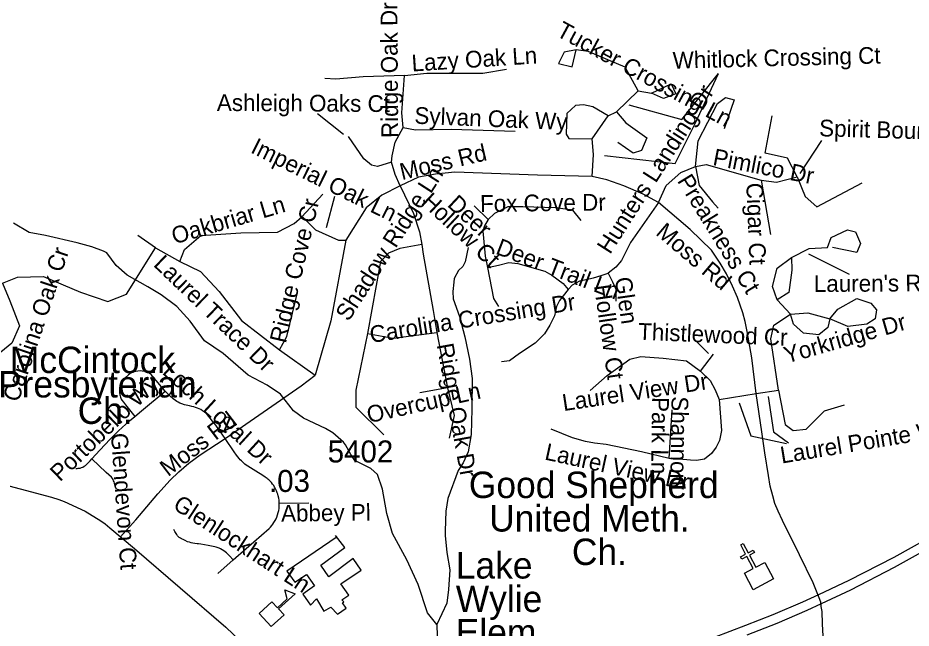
# Model space of a CAD drawing. Extents: x 1383679 to 1536984, y 460658 to 651027.
# Drawn here: x 1408689 to 1413754, y 502468 to 505931 of the extents above; entities that cross this region are included whole.
import ezdxf

# ---------------------------------------------------------------- set-up
doc = ezdxf.new("R2010")
doc.units = 0
for name, color, linetype in [('Exist Cultural Church CELL', 7, 'Continuous'), ('Exist Cultural Church Label', 7, 'Continuous'), ('Exist Cultural Church with Cemetery Label', 7, 'Continuous'), ('Exist Cultural Educational Facility Elementary CELL', 7, 'Continuous'), ('Exist Cultural Educational Facility Elementary Footprint', 7, 'Continuous'), ('Exist Hydrographic Creek Single Shore', 7, 'Continuous'), ('Exist Road Non-System Type 51', 7, 'Continuous'), ('Exist Road Non-System Type 51 Label', 7, 'Continuous'), ('Exist Road Primary NC UnDivided 4 Lane Attributed', 7, 'Continuous'), ('Exist Road Secondary Mileage Hundredths English Label', 7, 'Continuous'), ('Exist Road Secondary Type 51 Attributed', 7, 'Continuous'), ('Exist Road Secondary Type 51 Label', 7, 'Continuous'), ('Exist Road Secondary Type 51 Number Label', 7, 'Continuous')]:
    doc.layers.add(name, color=color, linetype=linetype)

msp = doc.modelspace()

# ---------------------------------------------------------------- linework, layer by layer
at = {"layer": 'Exist Cultural Church CELL'}
msp.add_lwpolyline([(1412808.6, 502780.3), (1412858.9, 502806.9), (1412823.4, 502874.3), (1412795.1, 502859.3), (1412787.6, 502873.5), (1412815.9, 502888.4), (1412787.9, 502941.6), (1412802, 502949.1), (1412830.1, 502895.9), (1412858.4, 502910.8), (1412865.9, 502896.7), (1412837.6, 502881.8), (1412873.1, 502814.4), (1412924.1, 502841.2), (1412973.8, 502747.1), (1412858.3, 502686.1)], close=True, dxfattribs=at)
at = {"layer": 'Exist Cultural Educational Facility Elementary CELL'}
msp.add_lwpolyline([(1410057, 502551.6), (1410129.3, 502617.7), (1410160.3, 502583.7), (1410215.7, 502634.4), (1410201.9, 502685.5), (1410261.6, 502663.4), (1410166.8, 502576.6), (1410197.9, 502542.7), (1410125.6, 502476.6)], close=True, dxfattribs=at)
at = {"layer": 'Exist Cultural Educational Facility Elementary Footprint'}
msp.add_lwpolyline([(1410500, 502985.4), (1410214.1, 502790.9), (1410258.9, 502728), (1410324.6, 502772.8), (1410371.3, 502708), (1410303.7, 502660.3), (1410347.5, 502597.4), (1410381.3, 502633.5), (1410424.5, 502563.7), (1410463.8, 502587.9), (1410501.9, 502547.8), (1410549.6, 502582.1), (1410529.6, 502610.7), (1410537.2, 502616.5), (1410525.8, 502628.8), (1410564.8, 502655.5), (1410519.5, 502720.1), (1410636.3, 502797.6), (1410589.6, 502862.4), (1410452.4, 502759.4), (1410407.6, 502826.2), (1410542, 502925.3), (1410490.7, 502993.8)], dxfattribs=at)
at = {"layer": 'Exist Hydrographic Creek Single Shore'}
for points in [[(1411063.7, 502487.9), (1411011, 502555.4), (1410958.1, 502716.5), (1410894.9, 502855.6), (1410813.6, 503005), (1410781.9, 503118), (1410756.6, 503256.4), (1410728.2, 503340.7), (1410690.8, 503373.4), (1410599.6, 503419.6), (1410576.3, 503453.7), (1410547.3, 503508.5), (1410535.6, 503522.7), (1410474.6, 503576.4), (1410433.1, 503601), (1410308.2, 503659.3), (1410251, 503700.7), (1410178.9, 503795.7), (1410101.9, 503847.3), (1409994.8, 503903.7), (1409853.2, 504026.3), (1409746.5, 504098.2), (1409666.6, 504209.7), (1409590.3, 504293.4), (1409501.5, 504359.1), (1409426.3, 504405), (1409307.6, 504471.4), (1409246.6, 504526.8), (1409194, 504597.5), (1409174.2, 504607.8), (1409108.6, 504631.3), (1409025, 504655.1), (1408845.8, 504696.5), (1408752, 504712.3), (1408663, 504765.8)], [(1411241.5, 504627.7), (1411226.1, 504547.6), (1411211.4, 504520), (1411187, 504498.4), (1411162.2, 504452.9), (1411161.7, 504430.7), (1411154.6, 504379.2), (1411157.9, 504337.3), (1411193.9, 504236.5), (1411223.7, 504121.8), (1411249.2, 503994.9), (1411265, 503884.6), (1411263.6, 503710.7), (1411258.9, 503567.2), (1411243, 503469), (1411213.7, 503405.6), (1411184.8, 503361.9), (1411127.7, 503203), (1411116.3, 503131), (1411112.2, 503019.5), (1411111.6, 502993.3), (1411121.8, 502897.1), (1411137.9, 502799.1), (1411131.5, 502686.8), (1411122.1, 502610.6), (1411063.7, 502487.9)], [(1411063.7, 502487.9), (1411069.9, 502294.1), (1411080, 502088), (1411089.7, 501971.2), (1411101.1, 501843), (1411167, 501529.8), (1411204.6, 501405.1), (1411274.6, 501193.7), (1411312.1, 501066.6), (1411376.4, 500877.3), (1411399.3, 500822.7)]]:
    msp.add_lwpolyline(points, dxfattribs=at)
at = {"layer": 'Exist Road Non-System Type 51'}
for p, q in [((1411356.4, 504787.1), (1411277.1, 504864.1)), ((1412560.6, 503926.4), (1412634.3, 504023.3)), ((1412665.2, 503765), (1412875.9, 503799.1)), ((1412382.4, 503430.6), (1412399, 503707.3)), ((1409822.7, 502778.9), (1409909.5, 502855.6))]:
    msp.add_line(p, q, dxfattribs=at)
for points in [[(1412205.5, 505517), (1412132.2, 505651), (1411922.4, 505739.6), (1411854.1, 505749.7), (1411785.9, 505737), (1411755.5, 505671.3), (1411831.4, 505653.5), (1411854.1, 505749.7)], [(1410880.6, 505603.3), (1411008.2, 505616.7), (1411180.6, 505616.7), (1411325.4, 505616.7), (1411459.8, 505640.1)], [(1410880.6, 505603.3), (1410646.2, 505596.7), (1410491.1, 505583.3), (1410429, 505586.6)], [(1410873.8, 505309), (1410866.9, 505392.6), (1410880.6, 505603.3)], [(1412014.7, 505150.5), (1412416.3, 505104), (1412530.5, 505332.5), (1412661.5, 505616)], [(1412154.2, 505438.2), (1412454.4, 505353.6), (1412661.5, 505616)], [(1412084.2, 505398.1), (1412205.5, 505517), (1412281.4, 505504.3), (1412392.6, 505557.4), (1412420.4, 505499.2), (1412349.6, 505473.9), (1412281.4, 505504.3)], [(1412531.7, 505086.9), (1412546.8, 505233.6), (1412655.5, 505446.1), (1412701, 505479), (1412751.6, 505466.4), (1412693.5, 505301.9)], [(1411945.1, 505243.8), (1412036.2, 505375.3), (1411950.2, 505425.9), (1411897.1, 505438.5), (1411851.6, 505433.5), (1411801, 505387.9), (1411798.5, 505271.6), (1411813.7, 505246.3), (1411945.1, 505243.8)], [(1410535.9, 505268.5), (1410387.9, 505387)], [(1412036.2, 505375.3), (1412084.2, 505398.1), (1412137.3, 505334.8), (1412256.1, 505251.3), (1412225.8, 505178), (1412177.7, 505162.8), (1412091.8, 505223.5)], [(1413108.1, 505028.7), (1413052.4, 505135), (1412926, 505162.8), (1412966.5, 505375.3)], [(1410808.3, 505111.6), (1410811.7, 505148.4), (1410828.9, 505225.3), (1410873.8, 505309)], [(1410873.8, 505309), (1410942.7, 505295.6), (1411146.1, 505298.9), (1411508.1, 505288.9)], [(1410808.3, 505111.6), (1410729, 505088.2), (1410694.5, 505094.9), (1410649.7, 505131.7), (1410563.5, 505258.8)], [(1411945.9, 505031.3), (1411952.8, 505155.1), (1411945.1, 505243.8)], [(1413125.1, 505048.8), (1413247.8, 505234.9)], [(1410856.5, 504977.8), (1410828.9, 505041.4), (1410808.3, 505111.6)], [(1412321.6, 504884.1), (1412364.8, 504980.7), (1412448.2, 505054), (1412531.7, 505086.9), (1412551.9, 504980.7), (1412627.7, 504887.1), (1412660.6, 504851.7)], [(1412531.7, 505086.9), (1412592.3, 505099.6), (1412903.3, 505011), (1412991.8, 504998.4), (1413108.1, 505028.7)], [(1411945.9, 505031.3), (1411635.6, 505038), (1411166.8, 505054.7), (1411056.5, 505044.7), (1410959.9, 505028), (1410856.5, 504977.8)], [(1412321.6, 504884.1), (1412235.4, 504931), (1412125.1, 504977.8), (1412028.6, 505011.3), (1411945.9, 505031.3)], [(1413108.1, 505028.7), (1413153.6, 504917.4), (1413219.3, 504859.3), (1413477.2, 504995.9)], [(1410856.5, 504977.8), (1410753.1, 504924.3), (1410663.5, 504854), (1410548.3, 504670.5)], [(1410856.5, 504977.8), (1410932.4, 504820.6), (1410966.8, 504716.9), (1410979.9, 504645.3), (1410987.5, 504589.8), (1411044.4, 504270), (1411064.7, 504145.6), (1411124.4, 503831.3), (1411162.1, 503674.1), (1411133.8, 503545.2)], [(1412903.3, 505011), (1412956.4, 504702.4)], [(1409607.8, 504547.9), (1409632.9, 504617.1), (1409727.1, 504695.6), (1409953.3, 504711.3), (1410160.6, 504714.5), (1410254.9, 504764.8), (1410298.9, 504802.5), (1410418.2, 504931.4)], [(1410439.5, 504740.8), (1410486, 504918.5)], [(1412321.6, 504884.1), (1412163.1, 504656.7), (1412111.5, 504553.7), (1412080.6, 504516.8), (1412035.4, 504482.2)], [(1412875.9, 503799.1), (1412850.5, 504001.9), (1412824.9, 504152.1), (1412812.9, 504207.8), (1412800.1, 504256.7), (1412770.1, 504344.7), (1412741.9, 504409.5), (1412706.8, 504479.2), (1412670.9, 504539.8), (1412645.2, 504578.8), (1412622.1, 504612.9), (1412500.9, 504730.3), (1412321.6, 504884.1)], [(1411883.8, 504780.4), (1411835.6, 504840.2), (1411738.2, 504852.8), (1411552.9, 504859.1), (1411468.1, 504859.1), (1411390.9, 504820.6), (1411356.4, 504787.1)], [(1410304.2, 504800), (1410376.1, 504728.1), (1410507.1, 504668.8), (1410548.3, 504670.5)], [(1411356.4, 504787.1), (1411335.7, 504750.3), (1411325.4, 504720.2), (1411328.8, 504680.1), (1411339.1, 504579.7), (1411351, 504514.5)], [(1413075.2, 504571.9), (1413176.3, 504622.5), (1413280, 504627.5), (1413300.2, 504685.7), (1413393.7, 504728.7), (1413439.2, 504716.1), (1413467.1, 504650.3), (1413446.8, 504599.7), (1413307.8, 504627.5)], [(1409468.3, 504626.5), (1409369, 504695.6)], [(1410548.3, 504670.5), (1410463.5, 504211.6), (1410374.3, 503903.5)], [(1408601.3, 504425.3), (1408686.1, 504459.9), (1408833.7, 504463), (1409044.2, 504375), (1409198.1, 504321.6), (1409304.9, 504362.5), (1409468.3, 504626.5)], [(1409468.3, 504626.5), (1409607.8, 504547.9), (1409724, 504491.3), (1409830.8, 504378.2), (1409956.5, 504214.7), (1410173.2, 504048.1), (1410374.3, 503903.5)], [(1410979.9, 504645.3), (1410854.2, 504623.3), (1410791.4, 504595.1), (1410744.3, 504547.9), (1410672, 504139.3), (1410606.1, 503818.7), (1410606.1, 503721.2), (1410763.1, 503564.1)], [(1413001.9, 503818.1), (1412958.9, 504109), (1412976.6, 504187.4), (1413070.1, 504250.6), (1413168.7, 504258.2), (1413292.6, 504222.8), (1413338.1, 504278.5), (1413446.8, 504339.2), (1413525.2, 504311.3), (1413558.1, 504273.4), (1413550.5, 504222.8), (1413502.5, 504192.5), (1413396.3, 504179.8), (1413292.6, 504222.8), (1413282.5, 504174.7), (1413231.9, 504131.7), (1413143.5, 504141.9), (1413087.8, 504192.5), (1413070.1, 504250.6), (1412994.3, 504331.6), (1412969, 504407.5), (1412994.3, 504511.2), (1413075.2, 504571.9), (1413077.7, 504498.5), (1413060, 504372.1), (1412994.3, 504331.6)], [(1413172.7, 504591.2), (1413402.8, 504476.1)], [(1411351, 504514.5), (1411415.2, 504528.3), (1411472.2, 504542.2), (1411524.5, 504537.5), (1411676.6, 504493.7), (1411717, 504470.7), (1411781.1, 504424.5), (1411809.7, 504390)], [(1411351, 504514.5), (1411386.6, 504339.2), (1411415.2, 504293.1)], [(1411809.7, 504390), (1411833.4, 504415.3), (1411876.2, 504438.4), (1411952.2, 504456.8), (1411997.4, 504468.4), (1412035.4, 504482.2)], [(1412035.4, 504482.2), (1412061.6, 504433.8), (1412080.6, 504392.3), (1412080.6, 504323.1)], [(1408601.3, 504425.3), (1408642.1, 504324.7), (1408698.7, 504183.3), (1408654.7, 504085.9), (1408538.5, 503991.6), (1408387.7, 503834.4), (1408334.3, 503667.8)], [(1410173.2, 504048.1), (1410214, 504123.6), (1410273.7, 504371.9)], [(1411809.7, 504390), (1411759.8, 504327.7), (1411743.1, 504293.1), (1411731.2, 504240.1), (1411706.3, 504188.2), (1411675.4, 504137.5), (1411622, 504085.9), (1411534, 504026.1), (1411477.5, 503985.3), (1411430.4, 503979)], [(1406959.6, 504223.3), (1407037.3, 504172.6), (1408317.7, 503410), (1408372.3, 503379.1), (1408441.3, 503342.5), (1408522.5, 503306.6), (1408879.4, 503210.4), (1408921.1, 503197.4), (1408951.9, 503186.9), (1409070.9, 503132.4), (1409159.8, 503076.8), (1409182.8, 503060), (1409210.2, 503037.9), (1409349.6, 502919.9), (1409868.6, 502473.9), (1409990.9, 502356.1), (1410024.8, 502313.2), (1410047, 502279.4), (1410104.6, 502177.8), (1410133.3, 502110.2), (1410384.7, 501515.1)], [(1410672, 504139.3), (1410816.6, 504114.1), (1411064.7, 504145.6)], [(1412605.1, 504025.9), (1412533.2, 504097.9)], [(1411934.4, 503817.4), (1412031.1, 503901.6), (1412159.2, 503994.4), (1412220.7, 504010.3), (1412348.7, 503999.3), (1412480.1, 503984.2), (1412560.6, 503926.4)], [(1409524.8, 503812.5), (1409452.8, 503897), (1409443.8, 503906.4), (1409438.5, 503910.8), (1409429.4, 503916.7), (1409419.7, 503921.3), (1409412.8, 503923.7), (1409407, 503925.2), (1409393.1, 503926.9), (1409381.2, 503927.4), (1409368.3, 503926.7), (1409357.6, 503924.7), (1409350.2, 503923), (1409342.9, 503920.7), (1409331.7, 503916.1), (1409324.4, 503911.3), (1409316.6, 503905.7), (1409299.8, 503890.8), (1409288.3, 503879.4), (1409281.3, 503871.4), (1409275.4, 503863.6), (1409272.2, 503858.2), (1409269.1, 503851.1), (1409267.4, 503845.5), (1409266.6, 503841.3), (1409265.6, 503832.8), (1409265.2, 503822.8), (1409265.2, 503814.8), (1409265.4, 503805.1), (1409266.6, 503792.6), (1409268.1, 503785.6), (1409270, 503778.7), (1409272.5, 503772.2), (1409275.2, 503767.3), (1409278.8, 503761.7), (1409286.8, 503750.5), (1409299.6, 503734.4), (1409351.3, 503668.9)], [(1412560.6, 503926.4), (1412615.3, 503873.4), (1412643.8, 503820.3), (1412665.2, 503765)], [(1409863.5, 503544.8), (1410295.7, 503843.8), (1410374.3, 503903.5)], [(1409351.3, 503668.9), (1409390.3, 503701), (1409524.8, 503812.5)], [(1409863.5, 503544.8), (1409838, 503582.2), (1409805.6, 503627.2), (1409793.1, 503643.1), (1409779.7, 503659.9), (1409772, 503668.8), (1409762.1, 503679.5), (1409754.1, 503688), (1409746.4, 503694.4), (1409736.4, 503701.7), (1409725.9, 503707.9), (1409717, 503712.6), (1409706.8, 503716.3), (1409701.6, 503718.4), (1409695.3, 503720.5), (1409686.1, 503723.1), (1409674.8, 503726), (1409661.3, 503729.3), (1409632.8, 503735.9), (1409618.3, 503740.5), (1409607.6, 503744.7), (1409597.9, 503749.4), (1409590.9, 503753.6), (1409582, 503759.6), (1409569.6, 503769), (1409562.9, 503774.5), (1409555.8, 503780.9), (1409538.9, 503797.2), (1409524.8, 503812.5)], [(1411124.4, 503831.3), (1410967.3, 503803)], [(1412875.9, 503799.1), (1413001.9, 503818.1)], [(1413001.9, 503818.1), (1413039.8, 503623.3), (1413085.3, 503590.4), (1413158.6, 503598), (1413262.3, 503701.7), (1413376, 503734.6)], [(1412665.2, 503765), (1412679.4, 503589.7), (1412668.2, 503533.2), (1412648.3, 503495.5), (1412622.2, 503458.6), (1412582.2, 503427), (1412536.7, 503419.4), (1412503.9, 503421.9), (1412438.1, 503427), (1412382.4, 503430.6)], [(1413233.8, 502640.5), (1413197.9, 502724.3), (1413121.8, 502883.7), (1413025.1, 503078.8), (1413000.3, 503132.7), (1412982.3, 503175.9), (1412969.5, 503218.2), (1412955.8, 503273.9), (1412945.5, 503334.5), (1412925, 503463.1), (1412907.9, 503582.7), (1412875.9, 503799.1)], [(1412944, 503782), (1412974.1, 503581.9), (1413059, 503518.8)], [(1412779.6, 503746.4), (1412845.3, 503559.9), (1413048.1, 503516)], [(1409108.3, 503427.9), (1409153.1, 503478.3), (1409211.6, 503540.2), (1409259.6, 503587.2), (1409321.1, 503644.1), (1409351.3, 503668.9)], [(1412382.4, 503430.6), (1412226.2, 503468.6), (1412024.1, 503510.6), (1411958.1, 503516.9), (1411907.8, 503526.4), (1411834.8, 503548.1), (1411713.6, 503596.5)], [(1409269.5, 502984.7), (1409357, 503082.7), (1409483.1, 503230.3), (1409551.8, 503307.1), (1409600.8, 503355.6), (1409658.1, 503405.1), (1409721.6, 503451.6), (1409863.5, 503544.8)], [(1410171, 503177.8), (1410170.9, 503181.6), (1410169.7, 503194), (1410167.9, 503205.6), (1410165.1, 503218.2), (1410162.4, 503227.7), (1410159.8, 503235.1), (1410155.2, 503246.6), (1410149.5, 503258.4), (1410143.8, 503268.6), (1410139.6, 503276.9), (1410133.2, 503285.8), (1410126.3, 503294.2), (1410119.5, 503301.6), (1410111.6, 503308.9), (1410105.6, 503313.9), (1410101.9, 503317), (1410091.4, 503324.7), (1410078, 503333.5), (1410038.1, 503359.1), (1410007.4, 503377.7), (1409992.5, 503387.2), (1409983.9, 503392.9), (1409975.4, 503399.3), (1409967.3, 503406.3), (1409956, 503417.1), (1409950, 503423.4), (1409943.7, 503430.5), (1409928.8, 503448.7), (1409915.2, 503467.6), (1409863.5, 503544.8)], [(1409016.5, 503373.5), (1409024.6, 503374.2), (1409029.9, 503374.9), (1409041.2, 503376.7), (1409048.6, 503378.7), (1409056.4, 503382), (1409064.5, 503386.6), (1409071.3, 503391.2), (1409079.2, 503398.3), (1409098.6, 503417), (1409108.3, 503427.9)], [(1409241.5, 503266.7), (1409238.8, 503281), (1409236.8, 503290.3), (1409234.4, 503297.8), (1409231.3, 503304.8), (1409228.2, 503310.6), (1409224.7, 503316.5), (1409219.2, 503323.8), (1409189.9, 503351.8), (1409108.3, 503427.9)], [(1409909.5, 502855.6), (1409982.8, 502920.4), (1410113, 503034.2), (1410120.4, 503041.7), (1410128.2, 503050.7), (1410134.5, 503058.7), (1410140.8, 503067.9), (1410147.2, 503078.4), (1410152.7, 503088.6), (1410156.9, 503098.4), (1410161.7, 503111.4), (1410165.2, 503123.3), (1410168, 503135.7), (1410169.8, 503147.3), (1410171, 503161), (1410171.2, 503172.1), (1410171, 503177.8)], [(1409909.5, 502855.6), (1409889.6, 502877.7), (1409883.4, 502883.7), (1409876.6, 502890.5), (1409871.4, 502895.1), (1409864.1, 502901.3), (1409857.1, 502906.4), (1409847.2, 502912.9), (1409837.7, 502918.2), (1409830.9, 502921.7), (1409825.4, 502924.1), (1409818.6, 502926.4), (1409812.3, 502928.3), (1409805, 502930.2), (1409786.3, 502934), (1409767.8, 502937.3), (1409746.7, 502940.6), (1409726.7, 502944.1), (1409713.8, 502945.8), (1409705.2, 502946.8), (1409691.6, 502948.5), (1409680.2, 502950.2), (1409670.7, 502952.2), (1409661.6, 502955), (1409650.7, 502958.5), (1409637.7, 502964.4), (1409625.5, 502970.5), (1409616.8, 502975.4), (1409610.8, 502978.7), (1409603.9, 502983.1), (1409597.8, 502987.5), (1409593.9, 502992.5), (1409590.3, 502998.7), (1409585.9, 503004.9), (1409579.6, 503015.8), (1409572.9, 503027.6)], [(1413255.6, 502422.7), (1413252.1, 502492.9), (1413249.2, 502561.6), (1413245, 502591.5), (1413242.4, 502614.7), (1413233.8, 502640.5)]]:
    msp.add_lwpolyline(points, dxfattribs=at)
at = {"layer": 'Exist Road Primary NC UnDivided 4 Lane Attributed'}
for points in [[(1412640.1, 502416.6), (1412816.7, 502485.5), (1412971.9, 502545.9), (1413140.7, 502618), (1413230.5, 502659.8), (1413403.2, 502739.6), (1413658, 502871.3), (1413935.6, 503026.3), (1414353.7, 503262.6), (1414637.9, 503426)], [(1412824.4, 502429.7), (1412995.1, 502497.1), (1413163.9, 502569.2), (1413246.8, 502607.1), (1413412.5, 502685.4), (1413660.3, 502814), (1413932.5, 502965.8), (1414396.3, 503227.7), (1414661.1, 503376.4)]]:
    msp.add_lwpolyline(points, dxfattribs=at)
at = {"layer": 'Exist Road Secondary Type 51 Attributed'}
msp.add_line((1410171, 503177.8), (1410338.6, 503179.4), dxfattribs=at)

# ---------------------------------------------------------------- texts
at = {"layer": 'Exist Cultural Church Label'}
for s, p in [('Good Shepherd', (1411246.2, 503206.2)), ('United Meth.', (1411361.3, 503016.2)), ('Ch.', (1411830.5, 502826.2))]:
    msp.add_text(s, height=150, rotation=0, dxfattribs=at).set_placement(p)
at = {"layer": 'Exist Cultural Church with Cemetery Label'}
for s, p in [('McCintock', (1408643.3, 503915.4)), ('Presbyterian', (1408576, 503777)), ('Ch.', (1409027.7, 503626.9))]:
    msp.add_text(s, height=150, dxfattribs=at).set_placement(p)
at = {"layer": 'Exist Cultural Educational Facility Elementary CELL'}
for s, p in [('Lake ', (1411172.1, 502749.4)), ('Wylie ', (1411172.1, 502559.4)), ('Elem. ', (1411172.1, 502369.4))]:
    msp.add_text(s, height=150, dxfattribs=at).set_placement(p)
at = {"layer": 'Exist Road Non-System Type 51 Label'}
for s, rotation, p in [('Ridge Oak Dr', 90.3999, (1410845.7, 505249.7)), ('Tucker Crossing Ln', 331.579, (1411735.7, 505832.4)), ('Lazy Oak Ln', 3.7139, (1410924.4, 505626.5)), ('Whitlock Crossing Ct', 1.4398, (1412403.3, 505642.5)), ('Hunters Landing Dr', 57.3659, (1412046.9, 504585)), ('Ashleigh Oaks Ct', 359.6255, (1409816.9, 505403.2)), ('Sylvan Oak Wy', 357.5886, (1410935.9, 505330.9)), ('Spirit Bound Wy', 358.341, (1413231.8, 505259.4)), ('Imperial Oak Ln', 333.706, (1410003.1, 505168.8)), ('Moss Rd', 13.214, (1410866.7, 505010)), ('Pimlico Dr', 348.9741, (1412625, 505097.2)), ('Shadow Ridge Ln', 57.2718, (1410563.9, 504203.8)), ('Preakness Ct', 301.4691, (1412425.2, 505006.7)), ('Cigar Ct', 272.2901, (1412819.3, 504993.7)), ('Hollow Ct', 316.9822, (1410971.1, 504878.5)), ('Deer ', 316.9822, (1411119.1, 504865.8)), ('Fox Cove Dr', 0.639, (1411310, 504830)), ('Oakbriar Ln', 16.3421, (1409576.3, 504645.6)), ('Ridge Cove Cr', 76.8078, (1410208, 504080.6)), ('Moss Rd', 319.6281, (1412300.9, 504704.1)), ('Deer Trail Ln', 339.0571, (1411392.6, 504593.5)), ('Carolina Oak Cr', 71.5015, (1408691.3, 503745.7)), ('Laurel Trace Dr', 316.1736, (1409452.5, 504526.5)), ("Lauren's Ridge Rd", 0.3744, (1413203.1, 504375.4)), ('Hollow Ct', 278.2676, (1411955.4, 504411.5)), ('Glen ', 278.2676, (1412073.8, 504453.8)), ('Carolina Crossing Dr', 9.2549, (1410692, 504085.5)), ('Yorkridge Dr', 15.9506, (1413048.4, 503969.1)), ('Thistlewood Cr', 357.6496, (1412204.9, 504105)), ('Ridge Oak Dr', 280.2354, (1411063.6, 504075.9)), ('Loch Loyal Dr', 317.5327, (1409502.2, 503914.8)), ('Laurel View Dr', 8.6406, (1411783.6, 503699.5)), ('Portobello Wy', 43.9431, (1408927.1, 503295.4)), ('Overcup Ln', 12.4371, (1410679.2, 503631)), ('Park Ln', 269.1893, (1412286, 503779.9)), ('Shannon ', 269.1893, (1412395.9, 503784.2)), ('Moss Rd', 37.4055, (1409540.3, 503324.4)), ('Laurel Pointe Wy', 9.4138, (1413020.7, 503401.8)), ('Glendevon Ct', 274.0304, (1409216.3, 503572.1)), ('Laurel View Dr', 347.7766, (1411671.4, 503425.5)), ('Glenlockhart Ln', 326.8705, (1409561.9, 503149.9))]:
    msp.add_text(s, height=95, rotation=rotation, dxfattribs=at).set_placement(p)
at = {"layer": 'Exist Road Secondary Mileage Hundredths English Label'}
msp.add_text('.03', height=125, rotation=0.5414, dxfattribs=at).set_placement((1410113.3, 503239.8))
at = {"layer": 'Exist Road Secondary Type 51 Label'}
msp.add_text('Abbey Pl', height=95, rotation=0.6985, dxfattribs=at).set_placement((1410181.7, 503072))
at = {"layer": 'Exist Road Secondary Type 51 Number Label'}
msp.add_text('5402', height=125, dxfattribs=at).set_placement((1410445.7, 503408))

doc.saveas('drawing.dxf')
